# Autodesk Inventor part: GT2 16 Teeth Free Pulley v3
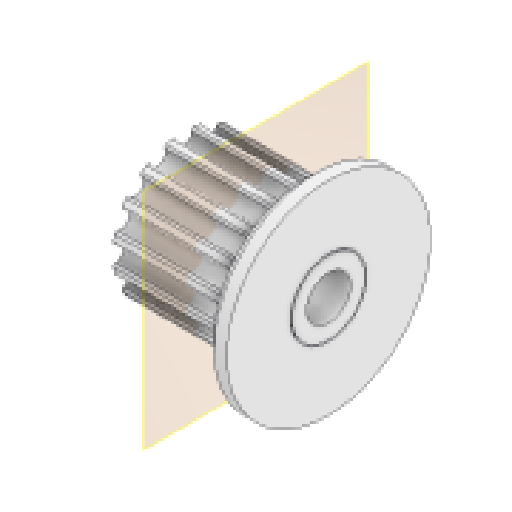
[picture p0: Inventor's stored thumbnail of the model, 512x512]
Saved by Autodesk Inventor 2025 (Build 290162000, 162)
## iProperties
Created: 2017-11
Part Number: GT2 16 Teeth Free Pulley v3
Material: Generico
Document SubType Name: Modeling
Designer: Administrator
Appearance: Generic
Title: GT2 16 Teeth Free Pulley v3
Author: Administrator
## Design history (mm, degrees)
feature "Body1"
node "Piano di lavoro1"
sketch "Schizzo1"
  geometry: C1 r 6.384 at (0, 0) reference; C2 r 7.761 at (0, 0); A1 r 0.55 centre (3.253, 3.253) between (2.878, 3.656) and (3.656, 2.878) reference; A2 r 0.16 centre (3.773, 2.769) between (3.902, 2.864) and (3.656, 2.878) reference; A3 r 4.84 centre (0, 0) between (4.139, 2.509) and (3.902, 2.864) reference; A4 r 0.16 centre (4.002, 2.426) between (4.058, 2.276) and (4.139, 2.509) reference; A5 r 0.55 centre (4.25, 1.76) between (4.058, 2.276) and (4.479, 1.26) reference; A6 r 0.16 centre (4.545, 1.115) between (4.701, 1.153) and (4.479, 1.26) reference; A7 r 4.84 centre (0, 0) between (4.784, 0.734) and (4.701, 1.153) reference; A8 r 0.16 centre (4.626, 0.71) between (4.62, 0.55) and (4.784, 0.734) reference; A9 r 0.55 centre (4.6, 0) between (4.62, 0.55) and (4.62, -0.55) reference; A10 r 0.16 centre (4.626, -0.71) between (4.784, -0.734) and (4.62, -0.55) reference; A11 r 4.84 centre (0, 0) between (4.701, -1.153) and (4.784, -0.734) reference; A12 r 0.16 centre (4.545, -1.115) between (4.479, -1.26) and (4.701, -1.153) reference; A13 r 0.55 centre (4.25, -1.76) between (4.479, -1.26) and (4.058, -2.276) reference; A14 r 0.16 centre (4.002, -2.426) between (4.139, -2.509) and (4.058, -2.276) reference; A15 r 4.84 centre (0, 0) between (3.902, -2.864) and (4.139, -2.509) reference; A16 r 0.16 centre (3.773, -2.769) between (3.656, -2.878) and (3.902, -2.864) reference; A17 r 0.55 centre (3.253, -3.253) between (3.656, -2.878) and (2.878, -3.656) reference; A18 r 0.16 centre (2.769, -3.773) between (2.864, -3.902) and (2.878, -3.656) reference; A19 r 4.84 centre (0, 0) between (2.509, -4.139) and (2.864, -3.902) reference; A20 r 0.16 centre (2.426, -4.002) between (2.276, -4.058) and (2.509, -4.139) reference; A21 r 0.55 centre (1.76, -4.25) between (2.276, -4.058) and (1.26, -4.479) reference; A22 r 0.16 centre (1.115, -4.545) between (1.153, -4.701) and (1.26, -4.479) reference; A23 r 4.84 centre (0, 0) between (0.734, -4.784) and (1.153, -4.701) reference; A24 r 0.16 centre (0.71, -4.626) between (0.55, -4.62) and (0.734, -4.784) reference; A25 r 0.55 centre (0, -4.6) between (0.55, -4.62) and (-0.55, -4.62) reference; A26 r 0.16 centre (-0.71, -4.626) between (-0.734, -4.784) and (-0.55, -4.62) reference; A27 r 4.84 centre (0, 0) between (-1.153, -4.701) and (-0.734, -4.784) reference; A28 r 0.16 centre (-1.115, -4.545) between (-1.26, -4.479) and (-1.153, -4.701) reference; A29 r 0.55 centre (-1.76, -4.25) between (-1.26, -4.479) and (-2.276, -4.058) reference; A30 r 0.16 centre (-2.426, -4.002) between (-2.509, -4.139) and (-2.276, -4.058) reference; A31 r 4.84 centre (0, 0) between (-2.864, -3.902) and (-2.509, -4.139) reference; A32 r 0.16 centre (-2.769, -3.773) between (-2.878, -3.656) and (-2.864, -3.902) reference; A33 r 0.55 centre (-3.253, -3.253) between (-2.878, -3.656) and (-3.656, -2.878) reference; A34 r 0.16 centre (-3.773, -2.769) between (-3.902, -2.864) and (-3.656, -2.878) reference; A35 r 4.84 centre (0, 0) between (-4.139, -2.509) and (-3.902, -2.864) reference; A36 r 0.16 centre (-4.002, -2.426) between (-4.058, -2.276) and (-4.139, -2.509) reference; A37 r 0.55 centre (-4.25, -1.76) between (-4.058, -2.276) and (-4.479, -1.26) reference; A38 r 0.16 centre (-4.545, -1.115) between (-4.701, -1.153) and (-4.479, -1.26) reference; A39 r 4.84 centre (0, 0) between (-4.784, -0.734) and (-4.701, -1.153) reference; A40 r 0.16 centre (-4.626, -0.71) between (-4.62, -0.55) and (-4.784, -0.734) reference; A41 r 0.55 centre (-4.6, 0) between (-4.62, -0.55) and (-4.62, 0.55) reference; A42 r 0.16 centre (-4.626, 0.71) between (-4.784, 0.734) and (-4.62, 0.55) reference; A43 r 4.84 centre (0, 0) between (-4.701, 1.153) and (-4.784, 0.734) reference; A44 r 0.16 centre (-4.545, 1.115) between (-4.479, 1.26) and (-4.701, 1.153) reference; A45 r 0.55 centre (-4.25, 1.76) between (-4.479, 1.26) and (-4.058, 2.276) reference; A46 r 0.16 centre (-4.002, 2.426) between (-4.139, 2.509) and (-4.058, 2.276) reference; A47 r 4.84 centre (0, 0) between (-3.902, 2.864) and (-4.139, 2.509) reference; A48 r 0.16 centre (-3.773, 2.769) between (-3.656, 2.878) and (-3.902, 2.864) reference; A49 r 0.55 centre (-3.253, 3.253) between (-3.656, 2.878) and (-2.878, 3.656) reference; A50 r 0.16 centre (-2.769, 3.773) between (-2.864, 3.902) and (-2.878, 3.656) reference; A51 r 4.84 centre (0, 0) between (-2.509, 4.139) and (-2.864, 3.902) reference; A52 r 0.16 centre (-2.426, 4.002) between (-2.276, 4.058) and (-2.509, 4.139) reference; A53 r 0.55 centre (-1.76, 4.25) between (-2.276, 4.058) and (-1.26, 4.479) reference; A54 r 0.16 centre (-1.115, 4.545) between (-1.153, 4.701) and (-1.26, 4.479) reference; A55 r 4.84 centre (0, 0) between (-0.734, 4.784) and (-1.153, 4.701) reference; A56 r 0.16 centre (-0.71, 4.626) between (-0.55, 4.62) and (-0.734, 4.784) reference; A57 r 0.55 centre (0, 4.6) between (-0.55, 4.62) and (0.55, 4.62) reference; A58 r 0.16 centre (0.71, 4.626) between (0.734, 4.784) and (0.55, 4.62) reference; A59 r 4.84 centre (0, 0) between (1.153, 4.701) and (0.734, 4.784) reference; A60 r 0.16 centre (1.115, 4.545) between (1.26, 4.479) and (1.153, 4.701) reference; A61 r 0.55 centre (1.76, 4.25) between (1.26, 4.479) and (2.276, 4.058) reference; A62 r 0.16 centre (2.426, 4.002) between (2.509, 4.139) and (2.276, 4.058) reference; A63 r 4.84 centre (0, 0) between (2.864, 3.902) and (2.509, 4.139) reference; A64 r 0.16 centre (2.769, 3.773) between (2.878, 3.656) and (2.864, 3.902) reference; 1 further point
  constraints: 1 centre point, 1 coincident
extrude "Estrusione1" cut sketch "Schizzo1" extent not by distance; stored distance "d0" = 0; taper "d1" = 0 deg
body "Solid1"
node "Linea chiusa proiettata1"
